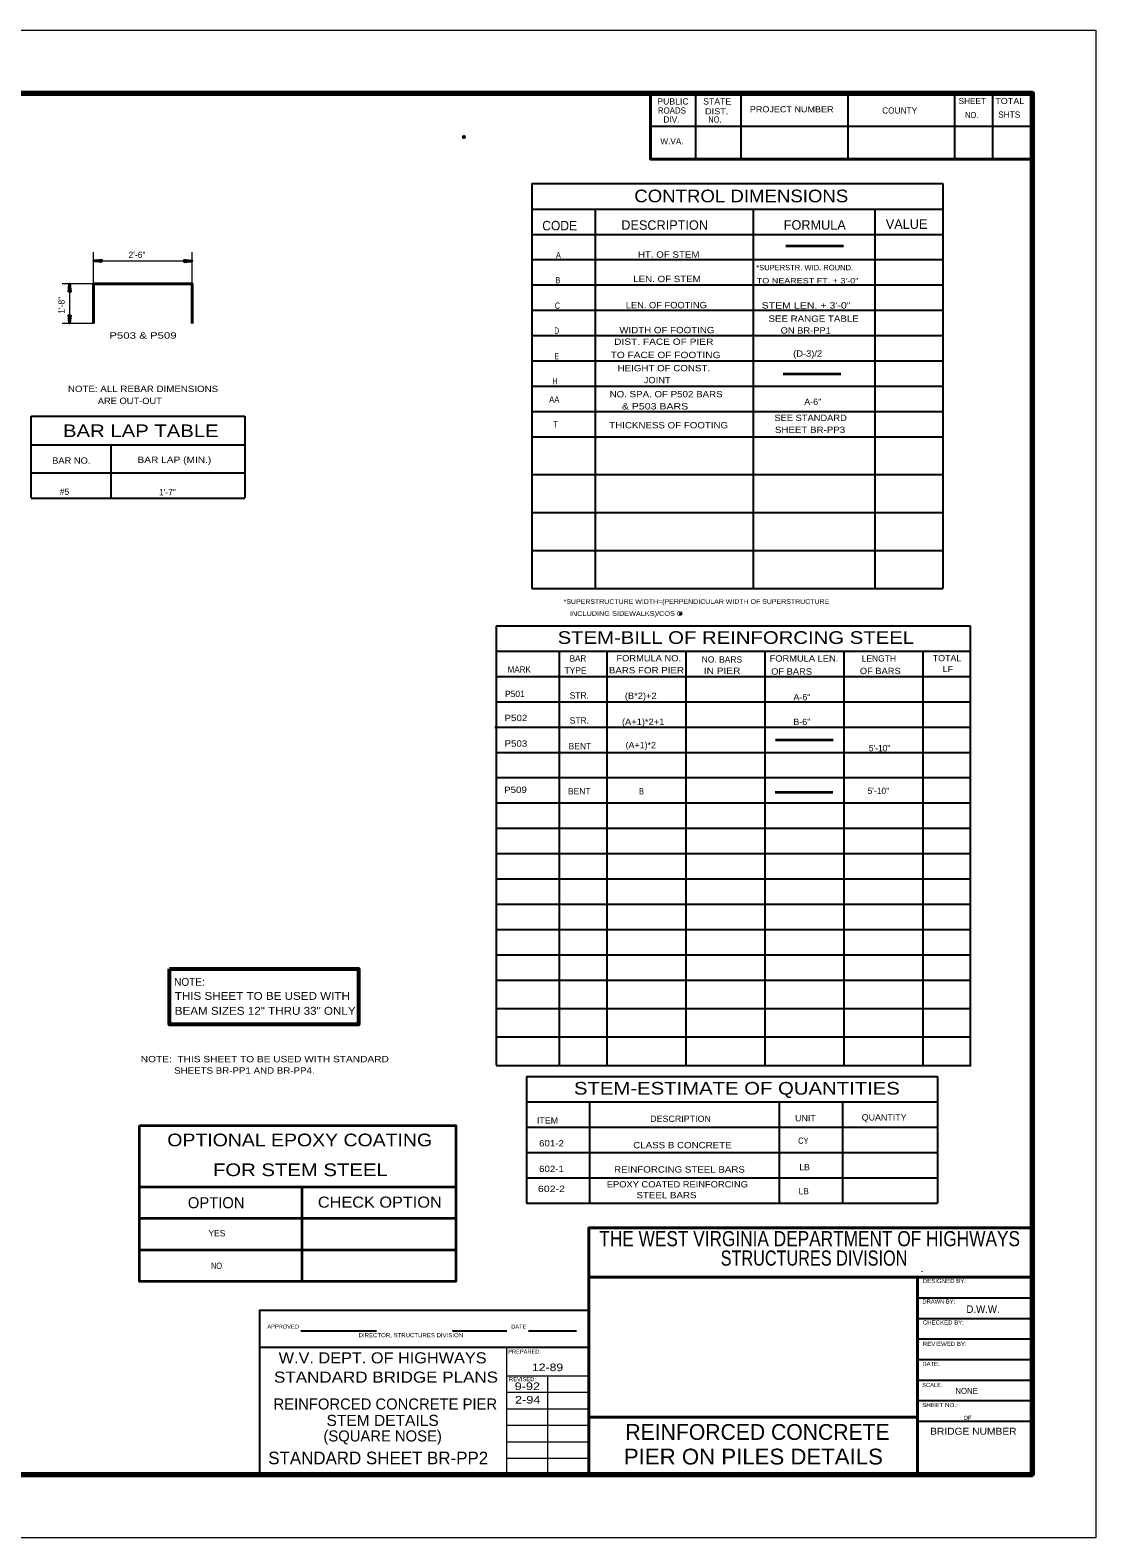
# Model space of a CAD drawing. Extents: x 6.34 to 9.53, y -1.46 to 0.53.
# Drawn here: x 8.128 to 9.533, y -1.459 to 0.528 of the extents above; entities that cross this region are included whole.
import ezdxf
from ezdxf.enums import TextEntityAlignment as Align

# ---------------------------------------------------------------- set-up
doc = ezdxf.new("R2010")
doc.units = 0
doc.header["$LTSCALE"] = 0.0033
doc.header["$PDMODE"] = 32
doc.header["$PDSIZE"] = 0.00165
doc.linetypes.add('DOTTED', pattern=[1.5, 0.3, -1.2])
doc.layers.add('1', color=7, linetype='Continuous', lineweight=40)

msp = doc.modelspace()

# ---------------------------------------------------------------- linework, layer by layer
at = {"layer": '1', "lineweight": 13}
for p, q in [((6.336, 0.527917), (9.532417, 0.527917)), ((9.532667, 0.52775), (9.532667, -1.458667)), ((8.211917, 0.19375), (8.211917, 0.235417)), ((8.212417, 0.223833), (8.34, 0.223833)), ((8.341583, 0.19375), (8.341583, 0.235417)), ((8.211917, 0.19375), (8.17025, 0.19375)), ((8.180167, 0.19375), (8.180167, 0.14225)), ((8.211917, 0.1415), (8.17025, 0.1415)), ((8.756083, -1.2075), (8.756083, -1.3755)), ((8.756083, -1.245417), (8.864417, -1.245417)), ((8.81025, -1.244917), (8.81025, -1.3755)), ((8.756083, -1.267083), (8.864417, -1.267083)), ((8.756083, -1.28875), (8.864417, -1.28875)), ((8.756083, -1.3105), (8.864417, -1.3105)), ((8.756083, -1.332167), (8.864417, -1.332167)), ((8.756083, -1.353833), (8.864417, -1.353833)), ((9.53275, -1.458833), (6.336, -1.458833))]:
    msp.add_line(p, q, dxfattribs=at)
at = {"layer": '1', "lineweight": 25}
for p, q in [((9.00525, 0.444583), (9.00525, 0.357917)), ((9.064833, 0.444583), (9.064833, 0.357917)), ((9.205667, 0.444583), (9.205667, 0.357917)), ((9.3465, 0.444583), (9.3465, 0.357917)), ((9.396333, 0.444583), (9.396333, 0.357917)), ((8.945667, 0.40125), (9.449417, 0.40125)), ((8.789583, 0.325667), (8.789583, -0.207833)), ((8.789583, 0.325667), (9.33125, 0.325667)), ((9.33125, 0.325667), (9.33125, -0.207833)), ((8.789583, 0.292167), (9.33125, 0.292167)), ((8.872917, 0.292167), (8.872917, -0.207833)), ((9.08125, 0.292167), (9.08125, -0.207833)), ((9.241583, 0.292167), (9.241583, -0.207833)), ((8.789583, 0.258833), (9.33125, 0.258833)), ((8.789583, 0.2255), (9.33125, 0.2255)), ((8.789583, 0.192167), (9.33125, 0.192167)), ((8.789583, 0.158833), (9.33125, 0.158833)), ((8.789583, 0.1255), (9.33125, 0.1255)), ((8.789583, 0.092167), (9.33125, 0.092167)), ((8.789583, 0.058833), (9.33125, 0.058833)), ((8.789583, 0.0255), (9.33125, 0.0255)), ((8.129667, 0.019333), (8.411083, 0.019333)), ((8.129667, -0.0885), (8.129667, 0.019333)), ((8.411083, 0.019333), (8.411083, -0.0885)), ((8.129667, -0.018417), (8.411083, -0.018417)), ((8.235167, -0.0885), (8.235167, -0.018417)), ((8.789583, -0.007833), (9.33125, -0.007833)), ((8.129667, -0.055333), (8.411083, -0.055333)), ((8.789583, -0.057833), (9.33125, -0.057833)), ((8.129667, -0.088833), (8.411083, -0.088833)), ((8.789583, -0.107833), (9.33125, -0.107833)), ((8.789583, -0.157833), (9.33125, -0.157833)), ((8.789583, -0.207833), (9.33125, -0.207833)), ((8.74225, -0.256917), (8.74225, -0.836167)), ((8.74225, -0.256917), (9.36725, -0.256917)), ((9.36725, -0.256917), (9.36725, -0.837583)), ((8.74225, -0.290417), (9.36725, -0.290417)), ((8.825583, -0.290417), (8.825583, -0.837)), ((8.888083, -0.290417), (8.888083, -0.836417)), ((8.99225, -0.290417), (8.99225, -0.836417)), ((9.096417, -0.290417), (9.096417, -0.836417)), ((9.200583, -0.290417), (9.200583, -0.837)), ((9.30475, -0.290417), (9.30475, -0.837583)), ((8.74225, -0.32375), (9.36725, -0.32375)), ((8.74225, -0.357083), (9.36725, -0.357083)), ((8.74075, -0.390417), (9.36725, -0.390417)), ((8.74225, -0.42375), (9.36725, -0.42375)), ((8.74225, -0.457083), (9.36725, -0.457083)), ((8.74225, -0.490417), (9.36725, -0.490417)), ((8.74225, -0.52375), (9.36725, -0.52375)), ((8.7415, -0.557083), (9.36725, -0.557083)), ((8.7415, -0.590417), (9.36725, -0.590417)), ((8.7415, -0.62375), (9.36725, -0.62375)), ((8.743083, -0.657083), (9.36725, -0.657083)), ((8.74225, -0.690417), (9.36725, -0.690417)), ((8.74225, -0.72375), (9.36725, -0.72375)), ((8.74225, -0.76125), (9.36725, -0.76125)), ((8.74225, -0.79875), (9.36725, -0.79875)), ((8.74225, -0.83625), (9.36725, -0.83625)), ((8.782167, -0.850917), (8.782167, -1.01775)), ((8.782167, -0.850917), (9.323833, -0.850917)), ((9.323833, -0.850917), (9.323833, -1.01775)), ((8.782167, -0.884417), (9.323833, -0.884417)), ((8.8655, -0.884417), (8.8655, -1.01775)), ((9.1155, -0.884417), (9.1155, -1.01775)), ((9.198833, -0.884417), (9.198833, -1.01775)), ((8.782167, -0.91775), (9.323833, -0.91775)), ((8.782167, -0.951083), (9.323833, -0.951083)), ((8.782167, -0.984417), (9.323833, -0.984417)), ((8.782167, -1.01775), (9.323833, -1.01775)), ((9.30375, -1.107833), (9.30375, -1.107333)), ((9.29775, -1.1425), (9.449417, -1.1425)), ((9.29775, -1.169583), (9.449417, -1.169583)), ((8.431083, -1.2075), (8.864417, -1.2075)), ((9.29775, -1.196667), (9.449417, -1.196667)), ((9.29775, -1.22375), (9.449417, -1.22375)), ((9.29775, -1.250833), (9.449417, -1.250833)), ((9.29775, -1.277917), (9.449417, -1.277917)), ((9.29775, -1.305083), (9.449417, -1.305083))]:
    msp.add_line(p, q, dxfattribs=at)
at = {"layer": '1', "lineweight": 35}
for p, q in [((9.12425, 0.24375), (9.20025, 0.24375)), ((8.2225, 0.223833), (8.211917, 0.223833)), ((8.22225, 0.223), (8.214417, 0.224)), ((8.22225, 0.223), (8.214417, 0.223833)), ((8.22225, 0.222833), (8.214417, 0.22375)), ((8.22225, 0.222833), (8.214417, 0.22375)), ((8.22225, 0.222917), (8.214417, 0.22375)), ((8.22225, 0.224917), (8.214917, 0.224083)), ((8.22225, 0.22475), (8.214917, 0.224)), ((8.22225, 0.224667), (8.214917, 0.223833)), ((8.222333, 0.2245), (8.215, 0.22375)), ((8.331, 0.223833), (8.341583, 0.223833)), ((8.331167, 0.223167), (8.3385, 0.223917)), ((8.33125, 0.224833), (8.339083, 0.223917)), ((8.33125, 0.224833), (8.339083, 0.223917)), ((8.33125, 0.22475), (8.339083, 0.223917)), ((8.33125, 0.224667), (8.339083, 0.223833)), ((8.33125, 0.224667), (8.339083, 0.223667)), ((8.33125, 0.223), (8.338583, 0.223833)), ((8.33125, 0.222917), (8.338583, 0.223667)), ((8.33125, 0.22275), (8.338583, 0.223583)), ((8.179167, 0.183417), (8.180083, 0.19125)), ((8.179167, 0.183417), (8.180083, 0.19125)), ((8.17925, 0.183417), (8.180083, 0.19125)), ((8.179333, 0.183417), (8.180167, 0.19125)), ((8.179333, 0.183417), (8.180333, 0.19125)), ((8.180833, 0.183333), (8.180083, 0.190667)), ((8.180167, 0.183167), (8.180167, 0.19375)), ((8.181, 0.183417), (8.180167, 0.19075)), ((8.181083, 0.183417), (8.180333, 0.19075)), ((8.18125, 0.183417), (8.180417, 0.19075)), ((8.179083, 0.151917), (8.179917, 0.144583)), ((8.17925, 0.151917), (8.18, 0.144583)), ((8.179333, 0.151917), (8.180167, 0.144583)), ((8.1795, 0.152), (8.18025, 0.144667)), ((8.181, 0.151917), (8.18, 0.144083)), ((8.180167, 0.152167), (8.180167, 0.141583)), ((8.181, 0.151917), (8.180167, 0.144083)), ((8.181167, 0.151917), (8.18025, 0.144083)), ((8.181167, 0.151917), (8.18025, 0.144083)), ((8.181083, 0.151917), (8.18025, 0.144083)), ((9.1205, 0.075167), (9.1965, 0.075167)), ((8.983667, -0.24075), (8.98775, -0.24075)), ((9.110583, -0.407083), (9.186583, -0.407083)), ((9.11, -0.476083), (9.186, -0.476083)), ((8.272417, -0.996083), (8.689083, -0.996083)), ((8.48675, -1.121417), (8.48675, -0.996417)), ((8.272417, -1.03775), (8.689083, -1.03775)), ((8.272417, -1.079417), (8.689083, -1.079417))]:
    msp.add_line(p, q, dxfattribs=at)
at = {"layer": '1'}
for p, q in [((8.864417, -1.115417), (9.449417, -1.115417)), ((9.29775, -1.115417), (9.29775, -1.3755)), ((8.864417, -1.299667), (9.29775, -1.299667))]:
    msp.add_line(p, q, dxfattribs=at)
at = {"layer": '1', "linetype": 'DOTTED', "lineweight": 25}
for p, q in [((8.48475, -1.186083), (8.756667, -1.186083)), ((8.784833, -1.186083), (8.848167, -1.186083))]:
    msp.add_line(p, q, dxfattribs=at)
at = {"layer": '1', "lineweight": 70}
msp.add_line((6.50275, -1.3755), (9.449417, -1.3755), dxfattribs=at)
msp.add_lwpolyline([(9.449417, -1.3755), (9.449417, 0.444583), (6.50275, 0.444583), (6.50275, -1.3755)], dxfattribs=at)
at = {"layer": '1'}
for points in [[(8.945667, 0.444583), (8.945667, 0.357917), (9.449417, 0.357917)], [(8.211917, 0.1415), (8.211917, 0.19375), (8.341583, 0.19375), (8.341583, 0.141167)], [(6.50275, -1.3755), (8.864417, -1.3755), (8.864417, -1.050417), (9.449417, -1.050417)]]:
    msp.add_lwpolyline(points, dxfattribs=at)
at = {"layer": '1', "lineweight": 35}
for points in [[(8.2225, 0.22275), (8.211917, 0.223833), (8.2225, 0.225), (8.221917, 0.223833)], [(8.22175, 0.22375), (8.217083, 0.223667), (8.217083, 0.22375), (8.218, 0.22375), (8.22175, 0.223667), (8.21875, 0.223583), (8.221917, 0.2235), (8.219667, 0.223417), (8.221917, 0.223333), (8.218417, 0.223583), (8.21375, 0.22375), (8.214667, 0.224), (8.213417, 0.224), (8.22175, 0.224), (8.219333, 0.224167), (8.221917, 0.224167), (8.216583, 0.22375), (8.221917, 0.224417)], [(8.331, 0.224917), (8.341583, 0.223833), (8.331, 0.222667), (8.331583, 0.223833)], [(8.33175, 0.223917), (8.336417, 0.224), (8.336417, 0.223917), (8.3355, 0.223917), (8.33175, 0.224), (8.33475, 0.224083), (8.331583, 0.224167), (8.333833, 0.22425), (8.331583, 0.224333), (8.335083, 0.224083), (8.33975, 0.223917), (8.338833, 0.223667), (8.340083, 0.223667), (8.33175, 0.223667), (8.334167, 0.2235), (8.331583, 0.2235), (8.336917, 0.223917), (8.331583, 0.22325)], [(8.179083, 0.183167), (8.180167, 0.19375), (8.181333, 0.183167), (8.180167, 0.18375)], [(8.180083, 0.183917), (8.18, 0.188583), (8.180083, 0.188583), (8.180083, 0.187667), (8.18, 0.183917), (8.179917, 0.186917), (8.179833, 0.18375), (8.17975, 0.186), (8.179667, 0.18375), (8.179917, 0.18725), (8.180083, 0.191917), (8.180333, 0.191), (8.180333, 0.19225), (8.180333, 0.183917), (8.1805, 0.186333), (8.1805, 0.18375), (8.180083, 0.189083), (8.18075, 0.18375)], [(8.18125, 0.152167), (8.180167, 0.141583), (8.179, 0.152167), (8.180167, 0.151583)], [(8.18025, 0.151417), (8.180333, 0.14675), (8.18025, 0.14675), (8.18025, 0.147667), (8.180333, 0.151417), (8.180417, 0.148417), (8.1805, 0.151583), (8.180583, 0.149333), (8.180667, 0.151583), (8.180417, 0.148083), (8.18025, 0.143417), (8.18, 0.144333), (8.18, 0.143083), (8.18, 0.151417), (8.179833, 0.149), (8.179833, 0.151583), (8.18025, 0.14625), (8.179583, 0.151583)], [(8.272417, -0.915667), (8.689083, -0.915667), (8.689083, -1.121083), (8.272417, -1.121083)]]:
    msp.add_lwpolyline(points, close=True, dxfattribs=at)
for points in [[(8.22175, 0.22375), (8.222167, 0.223), (8.221917, 0.22325), (8.22175, 0.223583), (8.2215, 0.2235), (8.221667, 0.223167), (8.221833, 0.223917), (8.222, 0.224417), (8.22225, 0.224833)], [(8.33175, 0.223917), (8.331333, 0.224667), (8.331583, 0.224417), (8.33175, 0.224083), (8.332, 0.224167), (8.331833, 0.2245), (8.331667, 0.22375), (8.3315, 0.22325), (8.33125, 0.222833)], [(8.180083, 0.183917), (8.179333, 0.1835), (8.179583, 0.18375), (8.179917, 0.183917), (8.179833, 0.184167), (8.1795, 0.184), (8.18025, 0.183833), (8.18075, 0.183667), (8.181167, 0.183417)], [(8.18025, 0.151417), (8.181, 0.151833), (8.18075, 0.151583), (8.180417, 0.151417), (8.1805, 0.151167), (8.180833, 0.151333), (8.180083, 0.1515), (8.179583, 0.151667), (8.179167, 0.151917)]]:
    msp.add_lwpolyline(points, dxfattribs=at)
at = {"layer": '1', "lineweight": 53}
msp.add_lwpolyline([(8.311833, -0.709), (8.561083, -0.709), (8.561083, -0.782167), (8.311833, -0.782167)], close=True, dxfattribs=at)
at = {"layer": '1', "lineweight": 25}
msp.add_lwpolyline([(8.431083, -1.3755), (8.431083, -1.15875), (8.864417, -1.15875)], dxfattribs=at)
at = {"layer": '1'}
for p in [(8.699917, 0.387083), (9.449417, -1.3755)]:
    msp.add_point(p, dxfattribs=at)

# ---------------------------------------------------------------- texts
for s, height, width, p in [('PUBLIC', 0.008167, 1.05, (8.975417, 0.429917)), ('STATE', 0.008167, 1.05, (9.033708, 0.429917)), ('TOTAL', 0.008084, 1.1, (9.419375, 0.4305)), ('ROADS', 0.008167, 0.95, (8.974, 0.418)), ('DIST.', 0.008167, 1.1, (9.033042, 0.416917)), ('PROJECT NUMBER', 0.008084, 1.1, (9.131875, 0.419667)), ('NO.', 0.008084, 0.9, (9.369208, 0.412083)), ('NO.', 0.008167, 0.9, (9.030708, 0.406083)), ('HEIGHT OF CONST.', 0.008334, 1.15, (8.963417, 0.078417)), ('H', 0.008334, 0.65, (8.819958, 0.061333)), ('JOINT', 0.008334, 1.1, (8.954625, 0.062667)), ('AA', 0.008334, 0.9, (8.819, 0.037167)), ('SEE STANDARD', 0.008334, 1.1, (9.156833, 0.012833)), ('T', 0.008334, 0.8, (8.820667, 0.004167)), ('THICKNESS OF FOOTING', 0.008334, 1.15, (8.969792, 0.003167)), ('SHEET BR-PP3', 0.008334, 1.15, (9.156083, -0.002833)), ('OPTIONAL EPOXY COATING', 0.01667, 1.15, (8.483458, -0.942833)), ('FOR STEM STEEL', 0.01667, 1.2, (8.484333, -0.982167)), ('THE WEST VIRGINIA DEPARTMENT OF HIGHWAYS', 0.02, 0.85, (9.155542, -1.074583)), ('STRUCTURES DIVISION', 0.02, 0.8, (9.161333, -1.100167)), ('NO', 0.008334, 0.8, (8.373833, -1.104417)), ('D.W.W.', 0.01, 0.95, (9.384083, -1.1625)), ('12-89', 0.01, 1.2, (8.810167, -1.239167)), ('9-92', 0.01, 1.25, (8.783542, -1.264083)), ('2-94', 0.01, 1.25, (8.783958, -1.281833)), ('BRIDGE NUMBER', 0.009166, 1.1, (9.371292, -1.322917))]:
    msp.add_text(s, height=height, dxfattribs=dict(at, width=width)).set_placement(p, align=Align.CENTER)
for s, height, p in [('SHEET', 0.008084, (9.369875, 0.4305)), ('COUNTY', 0.008167, (9.274167, 0.418)), ('SHTS', 0.008167, (9.418583, 0.412583)), ('DIV.', 0.008167, (8.9735, 0.406083)), ('W.VA.', 0.008084, (8.974083, 0.377417)), ('YES', 0.008334, (8.374333, -1.061583))]:
    msp.add_text(s, height=height, dxfattribs=at).set_placement(p, align=Align.CENTER)
for s, height, width, p in [('CONTROL DIMENSIONS', 0.01667, 1.1, (8.924417, 0.301083)), ('CODE', 0.0125, 0.95, (8.803167, 0.264083)), ('A', 0.008334, 0.75, (8.82125, 0.227417)), ('HT. OF STEM', 0.008334, 1.15, (8.92925, 0.228083)), ('*SUPERSTR. WID. ROUND. ', 0.007083, 1.05, (9.085167, 0.2115)), ('B', 0.008334, 0.75, (8.820583, 0.194417)), ('LEN. OF STEM', 0.008334, 1.15, (8.923083, 0.195917)), ('TO NEAREST FT. + 3\'-0"', 0.007083, 1.25, (9.085917, 0.194167)), ('C', 0.008334, 0.65, (8.819833, 0.16075)), ('LEN. OF FOOTING', 0.008334, 1.1, (8.913167, 0.1615)), ('STEM LEN. + 3\'-0"', 0.008334, 1.25, (9.09225, 0.161083)), ('SEE RANGE TABLE', 0.008334, 1.15, (9.101333, 0.143583)), ('P503 & P509', 0.008334, 1.35, (8.232583, 0.121417)), ('D', 0.008334, 0.65, (8.819, 0.127833)), ('DIST. FACE OF PIER', 0.008334, 1.2, (8.897917, 0.11325)), ('WIDTH OF FOOTING', 0.008334, 1.15, (8.90475, 0.128583)), ('ON BR-PP1', 0.008334, 1.1, (9.117333, 0.128083)), ('E', 0.008334, 0.75, (8.819, 0.094167)), ('TO FACE OF FOOTING', 0.008334, 1.2, (8.89325, 0.09575)), ('(D-3)/2', 0.008334, 1.1, (9.133833, 0.097583)), ('NOTE: ALL REBAR DIMENSIONS', 0.008334, 1.15, (8.178, 0.051083)), ('ARE OUT-OUT', 0.008334, 1.1, (8.217333, 0.035167)), ('NO. SPA. OF P502 BARS', 0.008334, 1.15, (8.891917, 0.044167)), ('A-6"', 0.008334, 1.05, (9.1485, 0.034083)), ('& P503 BARS', 0.008334, 1.25, (8.908, 0.028083)), ('BAR LAP TABLE', 0.01667, 1.2, (8.1715, -0.008333)), ('BAR NO.', 0.008334, 1.1, (8.15725, -0.043417)), ('BAR LAP (MIN.)', 0.008334, 1.2, (8.269667, -0.042417)), ('*SUPERSTRUCTURE WIDTH=(PERPENDICULAR WIDTH OF SUPERSTRUCTURE', 0.00625, 1.1, (8.83125, -0.228167)), ('INCLUDING SIDEWALKS)/COS O', 0.00625, 1.15, (8.839583, -0.244)), ('STEM-BILL OF REINFORCING STEEL', 0.01667, 1.2, (8.823417, -0.280833)), ('BAR', 0.008334, 0.95, (8.839333, -0.304167)), ('FORMULA NO.', 0.008334, 1.1, (8.900917, -0.303833)), ('FORMULA LEN.', 0.008334, 1.1, (9.10275, -0.304083)), ('TOTAL', 0.008334, 1.05, (9.31775, -0.303667)), ('MARK', 0.008334, 0.95, (8.7575, -0.318583)), ('BARS FOR PIER', 0.008334, 1.15, (8.890917, -0.319667)), ('IN PIER', 0.008334, 1.2, (9.016, -0.320417)), ('OF BARS', 0.008334, 1.1, (9.104833, -0.321333)), ('OF BARS', 0.008334, 1.1, (9.22175, -0.320667)), ('LF', 0.008334, 1.05, (9.330917, -0.318083)), ('(B*2)+2', 0.008334, 1.1, (8.912, -0.353417)), ('A-6"', 0.008334, 1.05, (9.13425, -0.355167)), ('P502', 0.008334, 1.15, (8.753417, -0.382583)), ('(A+1)*2+1', 0.008334, 1.1, (8.908167, -0.38775)), ('B-6"', 0.008334, 1.05, (9.134083, -0.387833)), ('P503', 0.008334, 1.15, (8.753417, -0.41625)), ('(A+1)*2', 0.008334, 1.05, (8.913, -0.418333)), ('P509', 0.008334, 1.15, (8.752917, -0.477333)), ('B', 0.008334, 0.75, (8.93075, -0.479083)), ('NOTE:', 0.01042, 0.95, (8.317917, -0.731417)), ('THIS SHEET TO BE USED WITH', 0.01042, 1.1, (8.318833, -0.749917)), ('BEAM SIZES 12" THRU 33" ONLY.', 0.01042, 1.1, (8.318833, -0.769583)), ('NOTE:  THIS SHEET TO BE USED WITH STANDARD', 0.008334, 1.2, (8.274, -0.832083)), ('SHEETS BR-PP1 AND BR-PP4.', 0.008334, 1.15, (8.318, -0.847167)), ('STEM-ESTIMATE OF QUANTITIES', 0.01667, 1.2, (8.844917, -0.87475)), ('ITEM', 0.008334, 1.05, (8.796083, -0.912833)), ('DESCRIPTION', 0.008334, 1.05, (8.945417, -0.91075)), ('UNIT', 0.008334, 1.05, (9.136333, -0.91)), ('QUANTITY', 0.008334, 1.05, (9.224167, -0.908917)), ('CY', 0.008334, 0.85, (9.140333, -0.939667)), ('601-2', 0.008334, 1.15, (8.798917, -0.943083)), ('CLASS B CONCRETE', 0.008334, 1.15, (8.923083, -0.945417)), ('602-1', 0.008334, 1.15, (8.798917, -0.97675)), ('REINFORCING STEEL BARS', 0.008334, 1.15, (8.897833, -0.9775)), ('EPOXY COATED REINFORCING', 0.008334, 1.1, (8.88825, -0.997083)), ('CHECK OPTION', 0.01458, 1.1, (8.507417, -1.02375)), ('602-2', 0.008334, 1.25, (8.797417, -1.003083)), ('STEEL BARS', 0.008334, 1.15, (8.927333, -1.011333)), ('DESIGNED BY:', 0.005418, 1.1, (9.304833, -1.123)), ('DRAWN BY:', 0.005418, 1.05, (9.30425, -1.150083)), ('DIRECTOR, STRUCTURES DIVISION', 0.005418, 1.1, (8.561083, -1.1945)), ('CHECKED BY:', 0.005418, 1.1, (9.304833, -1.17775)), ('REVIEWED BY:', 0.005418, 1.1, (9.304833, -1.205917)), ('W.V. DEPT. OF HIGHWAYS', 0.01458, 1.1, (8.45575, -1.228917)), ('DATE:', 0.005418, 1.05, (9.30425, -1.232417)), ('STANDARD BRIDGE PLANS', 0.01458, 1.15, (8.449583, -1.254333)), ('REVISED:', 0.005418, 1.05, (8.759333, -1.2525)), ('SCALE:', 0.005418, 1.05, (9.30375, -1.260083)), ('NONE', 0.008084, 0.95, (9.347583, -1.26925)), ('SHEET NO.:', 0.005418, 1.15, (9.30375, -1.286583)), ('STEM DETAILS', 0.01458, 1.05, (8.518833, -1.311333)), ('OF', 0.005418, 0.9, (9.358417, -1.303417)), ('PIER ON PILES DETAILS', 0.02083, 1.05, (8.91075, -1.362167))]:
    msp.add_text(s, height=height, dxfattribs=dict(at, width=width)).set_placement(p)
for s, height, p in [('VALUE', 0.0125, (9.255917, 0.266083)), ('DESCRIPTION ', 0.0125, (8.907333, 0.264833)), ('FORMULA', 0.0125, (9.121417, 0.265)), ('2\'-6"', 0.008334, (8.258, 0.22775)), ('#5', 0.008334, (8.167333, -0.084417)), ('1\'-7"', 0.008334, (8.298083, -0.085083)), ('NO. BARS', 0.008334, (9.013333, -0.3055)), ('LENGTH', 0.008334, (9.224167, -0.304167)), ('TYPE', 0.008334, (8.8325, -0.32)), ('P501', 0.008334, (8.754083, -0.350917)), ('STR.', 0.008334, (8.83925, -0.352833)), ('STR.', 0.008334, (8.839333, -0.385917)), ('BENT', 0.008334, (8.837917, -0.419667)), ('5\'-10"', 0.008334, (9.233583, -0.422333)), ('BENT', 0.008334, (8.837, -0.479167)), ('5\'-10"', 0.008334, (9.231917, -0.47875)), ('LB', 0.008334, (9.142083, -0.974417)), ('OPTION', 0.01458, (8.336, -1.0245)), ('LB', 0.008334, (9.140833, -1.006083)), ('APPROVED', 0.005417, (8.440833, -1.183167)), ('DATE', 0.005417, (8.76225, -1.183167)), ('PREPARED:', 0.005418, (8.75825, -1.216167)), ('REINFORCED CONCRETE PIER', 0.01458, (8.449, -1.28975)), ('REINFORCED CONCRETE', 0.02083, (8.91275, -1.32975)), ('(SQUARE NOSE)', 0.01458, (8.51475, -1.331833)), ('STANDARD SHEET BR-PP2', 0.01667, (8.442, -1.361917))]:
    msp.add_text(s, height=height, dxfattribs=at).set_placement(p)
msp.add_text('1\'-8"', height=0.008334, rotation=90, dxfattribs=at).set_placement((8.173583, 0.15425))

doc.saveas('drawing.dxf')
